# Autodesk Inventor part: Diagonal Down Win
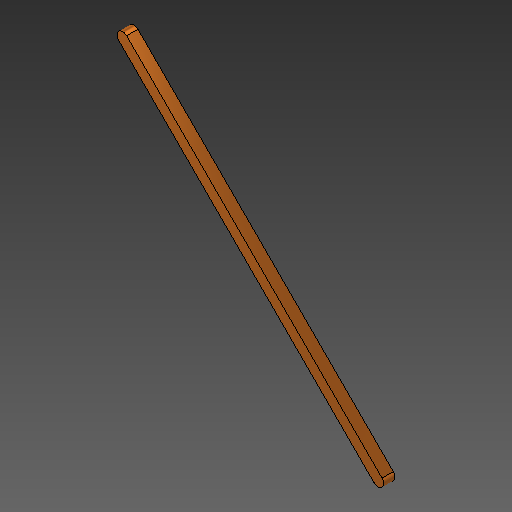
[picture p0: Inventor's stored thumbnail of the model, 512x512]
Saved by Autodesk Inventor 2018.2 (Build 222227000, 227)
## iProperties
Created: 2018-03
Part Number: Diagonal Down Win
Material: Gold
Document SubType Name: Modeling
Designer: PeterMaxwell-Stewart
Mass: 79.0948 g
Surface Area: 33.1781 cm^2
Volume: 4.09817 cm^3
Density: 19.3 g/cm^3
Appearance: Metal 1600F Hot
Author: PeterMaxwell-Stewart
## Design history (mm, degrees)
derived "O's and X's.ipt"
feature "Diagonal Down Win::O's and X's.ipt" dims "d0" = 10
tag "TaggingFeature1"
body "Solid1"
